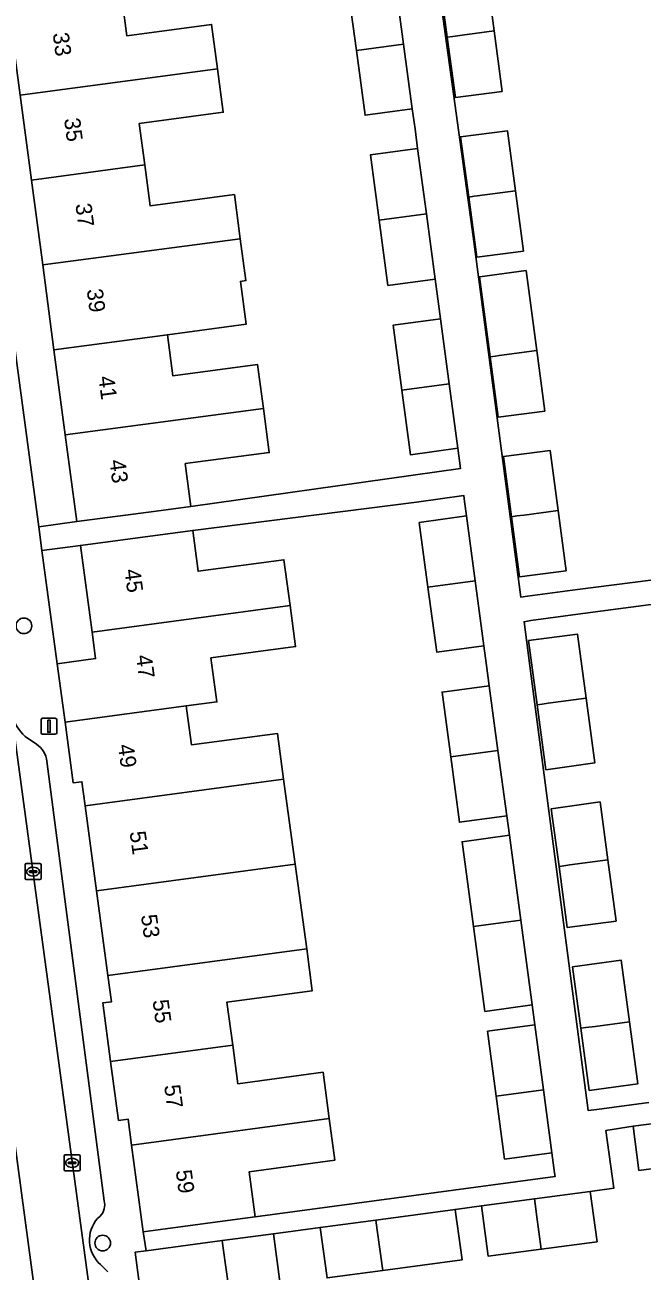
# Model space of a CAD drawing. Extents: x 163147 to 163550, y 380933 to 381639.
# Drawn here: x 163410.6 to 163449.2, y 381335.7 to 381413.5 of the extents above; entities that cross this region are included whole.
import ezdxf

# ---------------------------------------------------------------- set-up
doc = ezdxf.new("R2010")
doc.units = 0
for name, color, linetype in [('IMGEO_Boom', 7, 'Continuous'), ('IMGEO_Erf', 7, 'Continuous'), ('IMGEO_Kolk', 7, 'Continuous'), ('IMGEO_Lichtmast', 7, 'Continuous'), ('IMGEO_Pand', 7, 'Continuous'), ('IMGEO_Pand_nummerreeks', 7, 'Continuous'), ('IMGEO_Parkeervlak_open', 7, 'Continuous'), ('IMGEO_Rijbaan_lokaal_open', 7, 'Continuous'), ('IMGEO_Voetpad_open', 7, 'Continuous')]:
    doc.layers.add(name, color=color, linetype=linetype)

msp = doc.modelspace()

# ---------------------------------------------------------------- linework, layer by layer
at = {"layer": 'IMGEO_Boom'}
for centre in [(163410.55, 381375.989), (163415.473, 381337.418)]:
    msp.add_circle(centre, 0.489, dxfattribs=at)
at = {"layer": 'IMGEO_Erf'}
for points in [[(163452.493, 381450.557), (163435.219, 381448.391), (163432.641, 381448.046), (163432.294, 381447.999), (163432.106, 381447.974), (163432.721, 381443.105), (163438.61, 381400.319), (163441.596, 381377.783), (163442.021, 381377.839), (163445.139, 381378.255), (163461.983, 381380.414)], [(163416.643, 381415.398), (163416.979, 381412.864), (163422.279, 381413.567), (163422.647, 381410.796), (163423.007, 381408.081), (163417.753, 381407.384), (163418.097, 381404.789), (163418.435, 381402.243), (163423.704, 381402.942), (163424.071, 381400.183), (163424.419, 381397.56), (163424.078, 381397.515), (163424.434, 381394.832), (163419.515, 381394.177), (163419.855, 381391.612), (163425.148, 381392.314), (163425.512, 381389.574), (163425.877, 381386.82), (163420.628, 381386.124), (163420.983, 381383.447), (163434.88, 381385.407), (163437.829, 381385.823), (163437.66, 381387.083), (163434.711, 381386.667), (163434.167, 381390.726), (163433.622, 381394.788), (163436.575, 381395.181), (163436.408, 381396.425), (163436.243, 381397.653), (163433.29, 381397.26), (163432.744, 381401.337), (163432.198, 381405.416), (163435.15, 381405.81), (163434.985, 381407.038), (163434.817, 381408.289), (163431.865, 381407.895), (163431.321, 381411.951), (163430.777, 381416.014)], [(163462.183, 381378.958), (163445.472, 381376.751), (163442.221, 381376.313), (163441.8, 381376.246), (163442.25, 381372.849), (163445.794, 381345.703), (163446.336, 381345.774), (163449.587, 381346.212)], [(163452.239, 381342.383), (163448.977, 381341.961), (163448.62, 381344.728), (163446.913, 381344.458), (163447.401, 381340.844), (163445.937, 381340.648), (163446.358, 381337.497), (163442.871, 381337.031), (163439.564, 381336.589), (163439.134, 381339.738), (163437.492, 381339.519), (163437.577, 381338.893), (163437.614, 381338.623), (163437.921, 381336.37), (163432.972, 381335.709), (163429.489, 381335.244), (163429.06, 381338.392), (163426.138, 381338.001), (163426.568, 381334.854)]]:
    msp.add_lwpolyline(points, dxfattribs=at)
for points in [[(163411.022, 381403.847), (163410.318, 381409.154), (163409.613, 381414.462), (163408.909, 381419.77), (163408.25, 381424.737), (163405.797, 381424.407), (163411.479, 381382.181), (163413.854, 381382.502), (163413.134, 381387.927), (163412.43, 381393.234), (163411.726, 381398.54)], [(163439.923, 381413.164), (163440.427, 381409.389), (163437.508, 381408.998), (163437.004, 381412.772), (163436.502, 381416.529), (163439.422, 381416.92)], [(163441.257, 381403.176), (163441.76, 381399.409), (163438.842, 381399.02), (163438.339, 381402.785), (163437.837, 381406.541), (163440.755, 381406.932)], [(163442.591, 381393.187), (163443.095, 381389.411), (163440.179, 381389.02), (163439.674, 381392.796), (163439.006, 381397.793), (163439.349, 381397.839), (163439.639, 381397.878), (163441.924, 381398.184)], [(163443.925, 381383.2), (163444.428, 381379.435), (163441.512, 381379.046), (163441.009, 381382.809), (163440.507, 381386.562), (163443.424, 381386.953)], [(163437.927, 381362.501), (163440.879, 381362.898), (163440.716, 381364.114), (163437.764, 381363.717), (163437.216, 381367.804), (163436.673, 381371.85), (163439.625, 381372.247), (163439.457, 381373.501), (163439.291, 381374.742), (163436.339, 381374.346), (163435.794, 381378.408), (163435.253, 381382.444), (163438.203, 381382.86), (163438.083, 381383.751), (163438.032, 381384.134), (163435.082, 381383.718), (163421.096, 381381.952), (163421.438, 381379.403), (163426.793, 381380.122), (163427.178, 381377.251), (163427.521, 381374.692), (163422.237, 381373.983), (163422.606, 381371.239), (163420.698, 381370.983), (163420.74, 381370.669), (163421.025, 381368.544), (163426.385, 381369.264), (163426.769, 381366.402), (163427.494, 381361.101), (163428.218, 381355.802), (163428.569, 381353.188), (163423.234, 381352.472), (163423.595, 381349.784), (163423.919, 381347.376), (163429.238, 381348.09), (163429.626, 381345.197), (163429.976, 381342.592), (163424.625, 381341.874), (163425.003, 381339.058), (163443.738, 381341.568), (163443.706, 381341.805), (163443.538, 381343.061), (163440.586, 381342.666), (163440.059, 381346.597), (163439.515, 381350.657), (163442.467, 381351.054), (163442.3, 381352.296), (163439.348, 381351.899), (163438.637, 381357.2)], [(163414.081, 381381.011), (163411.68, 381380.688), (163412.631, 381373.623), (163415.029, 381373.945), (163414.808, 381375.59)], [(163445.668, 381371.472), (163446.214, 381367.424), (163443.168, 381366.991), (163442.62, 381371.062), (163442.08, 381375.068), (163445.128, 381375.478)], [(163447.031, 381361.362), (163447.544, 381357.543), (163444.497, 381357.133), (163443.982, 381360.953), (163443.497, 381364.556), (163446.543, 381364.988)], [(163445.344, 381350.84), (163444.826, 381354.685), (163447.874, 381355.095), (163448.392, 381351.25), (163448.915, 381347.37), (163445.867, 381346.959)]]:
    msp.add_lwpolyline(points, close=True, dxfattribs=at)
at = {"layer": 'IMGEO_Kolk'}
for p, q in [((163410.624, 381360.202), (163410.624, 381361.054)), ((163410.699, 381361.128), (163411.551, 381361.128)), ((163411.625, 381361.054), (163411.625, 381360.202)), ((163410.883, 381360.622), (163410.883, 381360.634)), ((163411.321, 381360.585), (163410.923, 381360.585)), ((163410.926, 381360.671), (163411.324, 381360.671)), ((163411.135, 381360.348), (163411.11, 381360.348)), ((163411.112, 381360.908), (163411.137, 381360.908)), ((163411.367, 381360.634), (163411.367, 381360.622)), ((163411.551, 381360.128), (163410.699, 381360.128)), ((163413.063, 381342.003), (163413.063, 381342.855)), ((163413.138, 381342.929), (163413.99, 381342.929)), ((163413.322, 381342.423), (163413.322, 381342.435)), ((163413.76, 381342.386), (163413.362, 381342.386)), ((163413.365, 381342.472), (163413.763, 381342.472)), ((163413.551, 381342.709), (163413.576, 381342.709)), ((163413.806, 381342.435), (163413.806, 381342.423)), ((163414.064, 381342.855), (163414.064, 381342.003)), ((163413.99, 381341.929), (163413.138, 381341.929)), ((163413.574, 381342.149), (163413.549, 381342.149))]:
    msp.add_line(p, q, dxfattribs=at)
for points in [[(163410.624, 381360.202), (163410.624, 381361.054)], [(163410.699, 381361.128), (163411.551, 381361.128)], [(163411.625, 381361.054), (163411.625, 381360.202)], [(163411.551, 381360.128), (163410.699, 381360.128)], [(163413.063, 381342.003), (163413.063, 381342.855)], [(163413.138, 381342.929), (163413.99, 381342.929)], [(163414.064, 381342.855), (163414.064, 381342.003)], [(163413.99, 381341.929), (163413.138, 381341.929)]]:
    msp.add_lwpolyline(points, dxfattribs=at)
for centre, radius, start, end in [((163410.701, 381361.052), 0.0765, 91.55205, 178.44795), ((163410.701, 381361.052), 0.0765, 91.55205, 178.44795), ((163411.549, 381361.052), 0.0765, 1.55205, 88.44795), ((163411.549, 381361.052), 0.0765, 1.55205, 88.44795), ((163410.701, 381360.204), 0.0765, 181.55205, 268.44795), ((163410.701, 381360.204), 0.0765, 181.55205, 268.44795), ((163410.923, 381360.631), 0.0403, 85.87752, 175.75265), ((163410.92, 381360.621), 0.0366, 178.93798, 274.71019), ((163411.324, 381360.628), 0.043, 264.86636, 352.45326), ((163411.328, 381360.633), 0.0386, 1.73085, 96.63898), ((163411.549, 381360.204), 0.0765, 271.55205, 358.44795), ((163411.549, 381360.204), 0.0765, 271.55205, 358.44795), ((163413.14, 381342.853), 0.0765, 91.55205, 178.44795), ((163413.14, 381342.853), 0.0765, 91.55205, 178.44795), ((163413.362, 381342.432), 0.0403, 85.87752, 175.75265), ((163413.359, 381342.422), 0.0366, 178.93798, 274.71019), ((163413.763, 381342.429), 0.043, 264.86636, 352.45326), ((163413.767, 381342.434), 0.0386, 1.73085, 96.63898), ((163413.988, 381342.853), 0.0765, 1.55205, 88.44795), ((163413.988, 381342.853), 0.0765, 1.55205, 88.44795), ((163413.14, 381342.005), 0.0765, 181.55205, 268.44795), ((163413.14, 381342.005), 0.0765, 181.55205, 268.44795), ((163413.988, 381342.005), 0.0765, 271.55205, 358.44795), ((163413.988, 381342.005), 0.0765, 271.55205, 358.44795)]:
    msp.add_arc(centre, radius, start, end, dxfattribs=at)
for centre, major_axis, ratio, start_param, end_param in [((163411.111, 381360.628), (-0.387, 0.002), 0.722429, 4.712389, 7.853982), ((163411.136, 381360.628), (-0.39, 0.002), 0.717154, 1.570796, 4.712389), ((163413.55, 381342.429), (-0.387, 0.002), 0.722429, 4.712389, 7.853982), ((163413.575, 381342.429), (-0.39, 0.002), 0.717154, 1.570796, 4.712389)]:
    msp.add_ellipse(centre, major_axis=major_axis, ratio=ratio, start_param=start_param, end_param=end_param, dxfattribs=at)
at = {"layer": 'IMGEO_Lichtmast'}
for p, q in [((163411.624, 381369.309), (163411.624, 381370.109)), ((163411.624, 381370.109), (163411.624, 381369.309)), ((163411.724, 381370.209), (163412.514, 381370.209)), ((163412.514, 381370.209), (163411.724, 381370.209)), ((163412.614, 381370.109), (163412.614, 381369.309)), ((163412.614, 381369.309), (163412.614, 381370.109)), ((163412.514, 381369.209), (163411.724, 381369.209)), ((163411.724, 381369.209), (163412.514, 381369.209))]:
    msp.add_line(p, q, dxfattribs=at)
msp.add_lwpolyline([(163412.044, 381370.084), (163412.194, 381370.084), (163412.194, 381369.334), (163412.044, 381369.334), (163412.044, 381370.084)], dxfattribs=at)
for centre, start, end in [((163411.724, 381370.109), 90, 180), ((163411.724, 381370.109), 90, 180), ((163412.514, 381370.109), 0, 90), ((163412.514, 381370.109), 360, 90), ((163411.724, 381369.309), 180, 270), ((163411.724, 381369.309), 180, 270), ((163412.514, 381369.309), 270, 0), ((163412.514, 381369.309), 270, 0)]:
    msp.add_arc(centre, 0.1, start, end, dxfattribs=at)
at = {"layer": 'IMGEO_Pand'}
for points in [[(163433.729, 381416.407), (163430.777, 381416.014), (163431.321, 381411.951), (163434.274, 381412.344)], [(163437.004, 381412.772), (163437.348, 381412.818), (163437.929, 381412.896), (163439.923, 381413.164), (163439.422, 381416.92), (163436.502, 381416.529)], [(163422.647, 381410.796), (163422.279, 381413.567), (163416.979, 381412.864), (163416.643, 381415.398), (163409.613, 381414.462), (163410.318, 381409.154)], [(163439.923, 381413.164), (163437.929, 381412.896), (163437.348, 381412.818), (163437.004, 381412.772), (163437.508, 381408.998), (163440.427, 381409.389)], [(163434.274, 381412.344), (163431.321, 381411.951), (163431.865, 381407.895), (163434.817, 381408.289)], [(163422.647, 381410.796), (163410.318, 381409.154), (163411.022, 381403.847), (163418.097, 381404.789), (163417.753, 381407.384), (163423.007, 381408.081)], [(163438.339, 381402.785), (163438.682, 381402.831), (163438.858, 381402.855), (163441.257, 381403.176), (163440.755, 381406.932), (163437.837, 381406.541)], [(163435.15, 381405.81), (163432.198, 381405.416), (163432.744, 381401.337), (163435.697, 381401.73)], [(163424.071, 381400.183), (163423.704, 381402.942), (163418.435, 381402.243), (163418.097, 381404.789), (163411.022, 381403.847), (163411.726, 381398.54)], [(163441.257, 381403.176), (163438.858, 381402.855), (163438.682, 381402.831), (163438.339, 381402.785), (163438.842, 381399.02), (163441.76, 381399.409)], [(163435.697, 381401.73), (163432.744, 381401.337), (163433.29, 381397.26), (163436.243, 381397.653)], [(163424.419, 381397.56), (163424.071, 381400.183), (163411.726, 381398.54), (163412.43, 381393.234), (163419.515, 381394.177), (163424.434, 381394.832), (163424.078, 381397.515)], [(163441.924, 381398.184), (163439.639, 381397.878), (163439.349, 381397.839), (163439.006, 381397.793), (163439.674, 381392.796), (163440.017, 381392.842), (163440.248, 381392.873), (163442.591, 381393.187)], [(163436.575, 381395.181), (163433.622, 381394.788), (163434.167, 381390.726), (163437.119, 381391.118)], [(163413.134, 381387.927), (163425.512, 381389.574), (163425.148, 381392.314), (163419.855, 381391.612), (163419.515, 381394.177), (163412.43, 381393.234)], [(163442.591, 381393.187), (163440.248, 381392.873), (163440.017, 381392.842), (163439.674, 381392.796), (163440.179, 381389.02), (163443.095, 381389.411)], [(163437.119, 381391.118), (163434.167, 381390.726), (163434.711, 381386.667), (163437.66, 381387.083)], [(163413.134, 381387.927), (163413.854, 381382.502), (163418.811, 381383.159), (163420.983, 381383.447), (163420.628, 381386.124), (163425.877, 381386.82), (163425.512, 381389.574)], [(163441.009, 381382.809), (163441.351, 381382.855), (163441.799, 381382.915), (163443.925, 381383.2), (163443.424, 381386.953), (163440.507, 381386.562)], [(163438.203, 381382.86), (163435.253, 381382.444), (163435.794, 381378.408), (163438.746, 381378.804)], [(163443.925, 381383.2), (163441.799, 381382.915), (163441.351, 381382.855), (163441.009, 381382.809), (163441.512, 381379.046), (163444.428, 381379.435)], [(163427.178, 381377.251), (163426.793, 381380.122), (163421.438, 381379.403), (163421.096, 381381.952), (163419.07, 381381.68), (163414.081, 381381.011), (163414.808, 381375.59)], [(163438.746, 381378.804), (163435.794, 381378.408), (163436.339, 381374.346), (163439.291, 381374.742)], [(163422.237, 381373.983), (163427.521, 381374.692), (163427.178, 381377.251), (163414.808, 381375.59), (163415.029, 381373.945), (163412.631, 381373.623), (163413.122, 381369.966), (163420.698, 381370.983), (163422.606, 381371.239)], [(163442.62, 381371.062), (163442.923, 381371.103), (163443.3, 381371.154), (163445.668, 381371.472), (163445.128, 381375.478), (163442.08, 381375.068)], [(163439.625, 381372.247), (163436.673, 381371.85), (163437.216, 381367.804), (163440.168, 381368.201)], [(163445.668, 381371.472), (163443.3, 381371.154), (163442.923, 381371.103), (163442.62, 381371.062), (163443.168, 381366.991), (163446.214, 381367.424)], [(163426.385, 381369.264), (163421.025, 381368.544), (163420.74, 381370.669), (163420.698, 381370.983), (163413.122, 381369.966), (163413.631, 381366.173), (163414.179, 381366.246), (163414.381, 381364.739), (163426.769, 381366.402)], [(163440.168, 381368.201), (163437.216, 381367.804), (163437.764, 381363.717), (163440.716, 381364.114)], [(163426.769, 381366.402), (163414.381, 381364.739), (163415.093, 381359.437), (163427.494, 381361.101)], [(163443.982, 381360.953), (163444.285, 381360.994), (163444.666, 381361.045), (163447.031, 381361.362), (163446.543, 381364.988), (163443.497, 381364.556)], [(163441.589, 381357.597), (163440.879, 381362.898), (163437.927, 381362.501), (163438.637, 381357.2)], [(163427.494, 381361.101), (163415.093, 381359.437), (163415.805, 381354.136), (163428.218, 381355.802)], [(163447.031, 381361.362), (163444.666, 381361.045), (163444.285, 381360.994), (163443.982, 381360.953), (163444.497, 381357.133), (163447.544, 381357.543)], [(163441.589, 381357.597), (163438.637, 381357.2), (163439.348, 381351.899), (163442.3, 381352.296)], [(163415.805, 381354.136), (163416.025, 381352.494), (163415.477, 381352.421), (163415.969, 381348.76), (163423.595, 381349.784), (163423.234, 381352.472), (163428.569, 381353.188), (163428.218, 381355.802)], [(163445.344, 381350.84), (163445.648, 381350.881), (163446.242, 381350.961), (163448.392, 381351.25), (163447.874, 381355.095), (163444.826, 381354.685)], [(163442.467, 381351.054), (163439.515, 381350.657), (163440.059, 381346.597), (163443.011, 381346.994)], [(163448.392, 381351.25), (163446.242, 381350.961), (163445.648, 381350.881), (163445.344, 381350.84), (163445.867, 381346.959), (163448.915, 381347.37)], [(163429.626, 381345.197), (163429.238, 381348.09), (163423.919, 381347.376), (163423.595, 381349.784), (163415.969, 381348.76), (163416.462, 381345.086), (163417.063, 381345.166), (163417.281, 381343.54)], [(163443.011, 381346.994), (163440.059, 381346.597), (163440.586, 381342.666), (163443.538, 381343.061)], [(163429.626, 381345.197), (163417.281, 381343.54), (163418.008, 381338.119), (163422.964, 381338.784), (163425.003, 381339.058), (163424.625, 381341.874), (163429.976, 381342.592)], [(163452.239, 381342.383), (163451.871, 381345.148), (163448.62, 381344.728), (163448.977, 381341.961)], [(163442.441, 381340.18), (163439.134, 381339.738), (163439.564, 381336.589), (163442.871, 381337.031), (163442.574, 381339.209), (163442.527, 381339.553)], [(163445.937, 381340.648), (163442.441, 381340.18), (163442.527, 381339.553), (163442.574, 381339.209), (163442.871, 381337.031), (163446.358, 381337.497)], [(163437.492, 381339.519), (163432.543, 381338.857), (163432.628, 381338.232), (163432.972, 381335.709), (163437.921, 381336.37), (163437.614, 381338.623), (163437.577, 381338.893)], [(163432.543, 381338.857), (163429.06, 381338.392), (163429.489, 381335.244), (163432.972, 381335.709), (163432.628, 381338.232)], [(163426.138, 381338.001), (163423.741, 381337.681), (163422.943, 381337.574), (163423.007, 381337.101), (163423.369, 381334.427), (163424.161, 381334.532), (163424.401, 381334.565), (163426.568, 381334.854)], [(163422.943, 381337.574), (163418.2, 381336.94), (163417.493, 381336.845), (163417.56, 381336.364), (163417.626, 381335.887), (163417.929, 381333.7), (163423.369, 381334.427), (163423.007, 381337.101)]]:
    msp.add_lwpolyline(points, close=True, dxfattribs=at)
at = {"layer": 'IMGEO_Parkeervlak_open'}
for points in [[(163409.808, 381370.393), (163417.023, 381316.959), (163417.13, 381316.166)], [(163412.274, 381317.247), (163413.073, 381316.642), (163413.31, 381316.453), (163413.709, 381315.897), (163413.628, 381316.496), (163406.464, 381369.736)], [(163411.336, 381368.595), (163410.627, 381369.081)], [(163415.566, 381340.059), (163411.991, 381367.526)], [(163415.155, 381338.956), (163415.32, 381339.107)], [(163415.788, 381335.626), (163415.345, 381336.073)]]:
    msp.add_lwpolyline(points, dxfattribs=at)
for centre, radius, start, end in [((163412.754, 381371.321), 3.089, 197.47558, 226.47236), ((163410.496, 381367.345), 1.506, 6.89413, 56.09932), ((163414.591, 381339.803), 1.008, 316.31125, 14.71176), ((163416.685, 381337.609), 2.038, 138.64082, 228.90027)]:
    msp.add_arc(centre, radius, start, end, dxfattribs=at)
at = {"layer": 'IMGEO_Rijbaan_lokaal_open'}
msp.add_lwpolyline([(163413.628, 381316.496), (163417.023, 381316.959), (163409.808, 381370.393), (163409.789, 381370.536), (163406.417, 381370.092), (163406.464, 381369.736)], close=True, dxfattribs=at)
at = {"layer": 'IMGEO_Voetpad_open'}
for points in [[(163461.983, 381380.414), (163445.139, 381378.255), (163442.021, 381377.839), (163441.596, 381377.783), (163438.61, 381400.319), (163432.721, 381443.105), (163432.106, 381447.974), (163432.294, 381447.999), (163432.641, 381448.046), (163435.219, 381448.391), (163452.493, 381450.557)], [(163417.929, 381333.7), (163417.626, 381335.887), (163417.56, 381336.364), (163417.493, 381336.845), (163418.2, 381336.94), (163418.008, 381338.119), (163417.281, 381343.54), (163417.063, 381345.166), (163416.462, 381345.086), (163415.969, 381348.76), (163415.477, 381352.421), (163416.025, 381352.494), (163415.805, 381354.136), (163415.093, 381359.437), (163414.381, 381364.739), (163414.179, 381366.246), (163413.631, 381366.173), (163413.122, 381369.966), (163412.631, 381373.623), (163411.68, 381380.688), (163411.479, 381382.181), (163405.797, 381424.407)], [(163433.729, 381416.407), (163434.274, 381412.344), (163434.817, 381408.289), (163434.985, 381407.038), (163435.15, 381405.81), (163435.697, 381401.73), (163436.243, 381397.653), (163436.408, 381396.425), (163436.575, 381395.181), (163437.119, 381391.118), (163437.66, 381387.083), (163437.829, 381385.823), (163434.88, 381385.407), (163420.983, 381383.447), (163418.811, 381383.159), (163413.854, 381382.502), (163411.479, 381382.181), (163411.68, 381380.688), (163414.081, 381381.011), (163419.07, 381381.68), (163421.096, 381381.952), (163435.082, 381383.718), (163438.032, 381384.134), (163438.083, 381383.751), (163438.203, 381382.86), (163438.746, 381378.804), (163439.291, 381374.742), (163439.457, 381373.501), (163439.625, 381372.247), (163440.168, 381368.201), (163440.716, 381364.114), (163440.879, 381362.898), (163441.589, 381357.597), (163442.3, 381352.296), (163442.467, 381351.054), (163443.011, 381346.994), (163443.538, 381343.061), (163443.706, 381341.805), (163443.738, 381341.568), (163425.003, 381339.058), (163422.964, 381338.784), (163418.008, 381338.119), (163418.2, 381336.94), (163422.943, 381337.574), (163423.741, 381337.681), (163426.138, 381338.001), (163429.06, 381338.392), (163432.543, 381338.857), (163437.492, 381339.519), (163439.134, 381339.738), (163442.441, 381340.18), (163445.937, 381340.648), (163447.401, 381340.844), (163446.913, 381344.458), (163448.62, 381344.728), (163451.871, 381345.148)], [(163449.587, 381346.212), (163446.336, 381345.774), (163445.794, 381345.703), (163442.25, 381372.849), (163441.8, 381376.246), (163442.221, 381376.313), (163445.472, 381376.751), (163462.183, 381378.958)], [(163410.627, 381369.081), (163411.336, 381368.595)], [(163411.991, 381367.526), (163415.566, 381340.059)], [(163415.32, 381339.107), (163415.155, 381338.956)], [(163415.345, 381336.073), (163415.788, 381335.626)]]:
    msp.add_lwpolyline(points, dxfattribs=at)
for centre, radius, start, end in [((163412.754, 381371.321), 3.089, 197.47558, 226.47236), ((163410.496, 381367.345), 1.506, 6.89413, 56.09932), ((163414.591, 381339.803), 1.008, 316.31125, 14.71176), ((163416.685, 381337.609), 2.038, 138.64082, 228.90027)]:
    msp.add_arc(centre, radius, start, end, dxfattribs=at)

# ---------------------------------------------------------------- texts
at = {"layer": 'IMGEO_Pand_nummerreeks'}
for s, rotation, p in [('33', 277.55816, (163412.349, 381413.005)), ('35', 277.55816, (163413.057, 381407.668)), ('37', 277.55816, (163413.765, 381402.332)), ('39', 277.5571, (163414.473, 381396.995)), ('41', 277.55816, (163415.197, 381391.546)), ('43', 277.55816, (163415.89, 381386.321)), ('45', 277.64138, (163416.828, 381379.484)), ('47', 277.64305, (163417.548, 381374.122)), ('49', 277.74045, (163416.417, 381368.537)), ('51', 277.74045, (163417.155, 381363.105)), ('53', 277.74045, (163417.863, 381357.897)), ('55', 277.73948, (163418.587, 381352.577)), ('57', 277.73948, (163419.31, 381347.257)), ('59', 277.73948, (163420.033, 381341.937))]:
    msp.add_text(s, height=1, rotation=rotation, dxfattribs=at).set_placement(p)

doc.saveas('drawing.dxf')
